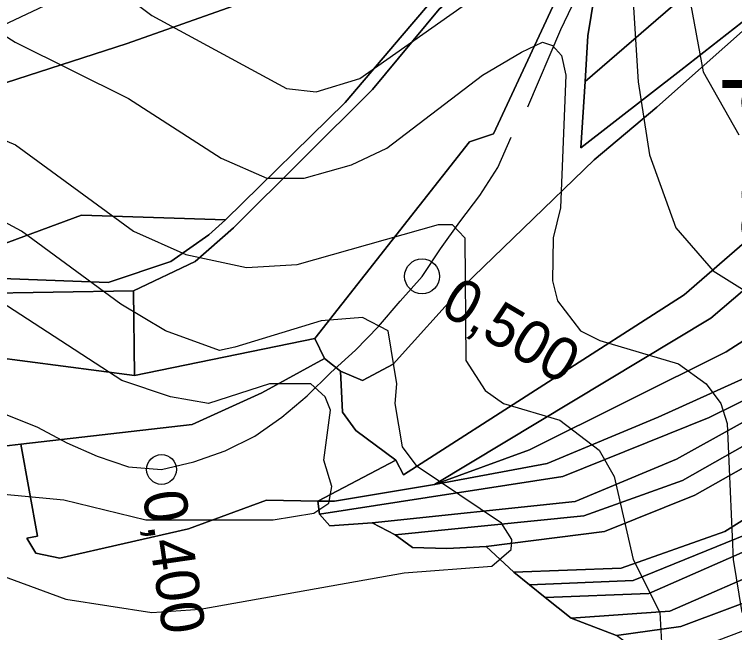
# Model space of a CAD drawing. Extents: x -510989 to -501240, y -1184665 to -1176098.
# Drawn here: x -509130.9 to -508913.6, y -1179477 to -1179290.6 of the extents above; entities that cross this region are included whole.
import ezdxf

# ---------------------------------------------------------------- set-up
doc = ezdxf.new("R2010")
doc.units = 0
for name, color, linetype in [('lesni_pozemek', 7, 'Continuous'), ('NAVRH_rozvodnice', 7, 'Continuous'), ('orna_puda', 7, 'Continuous'), ('ostatni_plocha_x_neplodna_puda', 7, 'Continuous'), ('ostatni_plocha_x_ostatni_komunikace', 7, 'Continuous'), ('STAV_systematicke_odvodneni', 7, 'Continuous'), ('STAV_vyrazne_udolnice', 7, 'Continuous'), ('trasovani_toku', 7, 'Continuous'), ('trvaly_travni_porost', 7, 'Continuous'), ('vodni_plocha_x_zamokrena_plocha', 7, 'Continuous'), ('vrstevnice_01', 7, 'Continuous'), ('vrstevnice_02', 7, 'Continuous')]:
    doc.layers.add(name, color=color, linetype=linetype)

msp = doc.modelspace()

# ---------------------------------------------------------------- linework, layer by layer
at = {"layer": 'lesni_pozemek'}
for points in [[(-508606.71, -1179124.06), (-508602.46, -1179133.28), (-508620.45, -1179146.82), (-508664.63, -1179178.45), (-508745.73, -1179236.53), (-508795.13, -1179278.48), (-508821.2, -1179300.02), (-508865.34, -1179335.02), (-508920.75, -1179382.22), (-509004.18, -1179432.41), (-509034.35, -1179437.44), (-509039.3, -1179437.44), (-509015.83, -1179425.01), (-509013.45, -1179429.49), (-508928.79, -1179375.15), (-508868.76, -1179323.15), (-508825.42, -1179288.74), (-508804.74, -1179272.32), (-508751.85, -1179228.29), (-508670.83, -1179171.13)], [(-508602.46, -1179133.28), (-508597.41, -1179144.21), (-508627.17, -1179165.02), (-508677.1, -1179199.34), (-508739.74, -1179246.04), (-508793.88, -1179292.04), (-508819.69, -1179313.98), (-508856.75, -1179347.13), (-508895.95, -1179379.44), (-508916.18, -1179392.38), (-508975.49, -1179421.94), (-509004.18, -1179432.41), (-508920.75, -1179382.22), (-508865.34, -1179335.02), (-508821.2, -1179300.02), (-508795.13, -1179278.48), (-508745.73, -1179236.53), (-508664.63, -1179178.45), (-508620.45, -1179146.82)], [(-508782.97, -1179140.01), (-508801.27, -1179151.69), (-508813.83, -1179164.87), (-508835.52, -1179196.99), (-508826.67, -1179217.53), (-508818.83, -1179228.85), (-508851, -1179251.48), (-508870.07, -1179264.89), (-508904.41, -1179287.59), (-508929.85, -1179307.42), (-508960, -1179330.91), (-508958.72, -1179310.91), (-508932.22, -1179288.07), (-508909.87, -1179281.03), (-508901.7, -1179270), (-508891.13, -1179223.99), (-508903.93, -1179198.15), (-508900.07, -1179195.8), (-508839.52, -1179165.73), (-508783.82, -1179133.81)], [(-508597.41, -1179144.21), (-508593.51, -1179152.66), (-508681.27, -1179215.37), (-508736.62, -1179256.95), (-508810.44, -1179322.38), (-508849.99, -1179360.81), (-508891.52, -1179391.72), (-508936.65, -1179412.11), (-508970.12, -1179426.03), (-509004.18, -1179432.41), (-508975.49, -1179421.94), (-508916.18, -1179392.38), (-508895.95, -1179379.44), (-508856.75, -1179347.13), (-508819.69, -1179313.98), (-508793.88, -1179292.04), (-508739.74, -1179246.04), (-508677.1, -1179199.34), (-508627.17, -1179165.02)], [(-508593.51, -1179152.66), (-508591.09, -1179157.9), (-508636.59, -1179188.7), (-508678.28, -1179219.08), (-508735.28, -1179262.56), (-508773.87, -1179296.38), (-508846.78, -1179363.36), (-508887.12, -1179395.25), (-508921.3, -1179412.21), (-508965.45, -1179429.97), (-509038.84, -1179441.31), (-509039.3, -1179437.44), (-509034.35, -1179437.44), (-509004.18, -1179432.41), (-508970.12, -1179426.03), (-508936.65, -1179412.11), (-508891.52, -1179391.72), (-508849.99, -1179360.81), (-508810.44, -1179322.38), (-508736.62, -1179256.95), (-508681.27, -1179215.37)], [(-508591.09, -1179157.9), (-508589, -1179164.01), (-508617.38, -1179182.87), (-508657.73, -1179210.41), (-508676.52, -1179223.23), (-508729.39, -1179266.54), (-508758.46, -1179289.1), (-508774.13, -1179302.13), (-508810.01, -1179338.18), (-508874.37, -1179393.27), (-508931.1, -1179424.79), (-508961.7, -1179437.48), (-509022.9, -1179443.92), (-509035.74, -1179444.84), (-509038.84, -1179441.31), (-508965.45, -1179429.97), (-508921.3, -1179412.21), (-508887.12, -1179395.25), (-508846.78, -1179363.36), (-508773.87, -1179296.38), (-508735.28, -1179262.56), (-508678.28, -1179219.08), (-508636.59, -1179188.7)], [(-508589, -1179164.01), (-508588.4, -1179169.09), (-508625.48, -1179194.26), (-508672.32, -1179226.71), (-508705.37, -1179253.14), (-508769.81, -1179304.68), (-508807.77, -1179341.74), (-508874.49, -1179400.1), (-508929.34, -1179431.21), (-508959.11, -1179441.81), (-509015.99, -1179447.57), (-509022.9, -1179443.92), (-508961.7, -1179437.48), (-508931.1, -1179424.79), (-508874.37, -1179393.27), (-508810.01, -1179338.18), (-508774.13, -1179302.13), (-508758.46, -1179289.1), (-508729.39, -1179266.54), (-508676.52, -1179223.23), (-508657.73, -1179210.41), (-508617.38, -1179182.87)], [(-508588.4, -1179169.09), (-508587.71, -1179174.96), (-508603.94, -1179186.13), (-508637.9, -1179209.19), (-508673.41, -1179233.85), (-508699.31, -1179253.96), (-508766.89, -1179308.93), (-508803.79, -1179344.12), (-508868.78, -1179403.52), (-508925.57, -1179435.6), (-508952.84, -1179446.55), (-508988.55, -1179451.08), (-509000.44, -1179451.65), (-509010.76, -1179451.37), (-509015.99, -1179447.57), (-508959.11, -1179441.81), (-508929.34, -1179431.21), (-508874.49, -1179400.1), (-508807.77, -1179341.74), (-508769.81, -1179304.68), (-508705.37, -1179253.14), (-508672.32, -1179226.71), (-508625.48, -1179194.26)], [(-508603.94, -1179186.13), (-508587.71, -1179174.96), (-508588.59, -1179186.18), (-508626.11, -1179212.1), (-508659.61, -1179236.76), (-508688.25, -1179258.6), (-508764.65, -1179319.51), (-508798.46, -1179354.18), (-508849.61, -1179401.5), (-508871.75, -1179418.41), (-508916.51, -1179446.55), (-508947.82, -1179457.65), (-508980.25, -1179458.83), (-508988.55, -1179451.08), (-508952.84, -1179446.55), (-508925.57, -1179435.6), (-508868.78, -1179403.52), (-508803.79, -1179344.12), (-508766.89, -1179308.93), (-508699.31, -1179253.96), (-508673.41, -1179233.85), (-508637.9, -1179209.19)], [(-508588.59, -1179186.18), (-508588.71, -1179193.66), (-508628.09, -1179219.81), (-508656.48, -1179239.5), (-508685.64, -1179262.11), (-508760.46, -1179322.97), (-508793.58, -1179355.94), (-508851.05, -1179409), (-508870.8, -1179423.99), (-508909.79, -1179447.4), (-508944.19, -1179461.32), (-508975.49, -1179462.64), (-508980.25, -1179458.83), (-508947.82, -1179457.65), (-508916.51, -1179446.55), (-508871.75, -1179418.41), (-508849.61, -1179401.5), (-508798.46, -1179354.18), (-508764.65, -1179319.51), (-508688.25, -1179258.6), (-508659.61, -1179236.76), (-508626.11, -1179212.1)], [(-508588.71, -1179193.66), (-508588.83, -1179200.61), (-508619.49, -1179220.52), (-508657.63, -1179249.27), (-508680.32, -1179266.36), (-508719.21, -1179297.41), (-508752.88, -1179324.28), (-508792.02, -1179362.68), (-508852.01, -1179417.08), (-508878.3, -1179434.77), (-508911.28, -1179452.86), (-508939.5, -1179465.29), (-508970.76, -1179466.44), (-508975.49, -1179462.64), (-508944.19, -1179461.32), (-508909.79, -1179447.4), (-508870.8, -1179423.99), (-508851.05, -1179409), (-508793.58, -1179355.94), (-508760.46, -1179322.97), (-508685.64, -1179262.11), (-508656.48, -1179239.5), (-508628.09, -1179219.81)], [(-508588.83, -1179200.61), (-508588.99, -1179210.23), (-508613.11, -1179226.54), (-508646.02, -1179248.81), (-508746.19, -1179326.59), (-508785.46, -1179363.77), (-508847.48, -1179420.93), (-508867.89, -1179435.75), (-508900.87, -1179456.48), (-508933.12, -1179470.58), (-508962.93, -1179472.72), (-508970.76, -1179466.44), (-508939.5, -1179465.29), (-508911.28, -1179452.86), (-508878.3, -1179434.77), (-508852.01, -1179417.08), (-508792.02, -1179362.68), (-508752.88, -1179324.28), (-508719.21, -1179297.41), (-508680.32, -1179266.36), (-508657.63, -1179249.27), (-508619.49, -1179220.52)], [(-508588.99, -1179210.23), (-508589.14, -1179219.49), (-508640.89, -1179254.11), (-508673.22, -1179276.82), (-508695.6, -1179292.56), (-508745.95, -1179333.82), (-508790.53, -1179376.59), (-508841.59, -1179423.24), (-508901.03, -1179464.49), (-508929.84, -1179475.18), (-508949.21, -1179477.96), (-508962.93, -1179472.72), (-508933.12, -1179470.58), (-508900.87, -1179456.48), (-508867.89, -1179435.75), (-508847.48, -1179420.93), (-508785.46, -1179363.77), (-508746.19, -1179326.59), (-508646.02, -1179248.81), (-508613.11, -1179226.54)], [(-508589.14, -1179219.49), (-508589.27, -1179227.34), (-508618.53, -1179246.98), (-508666.63, -1179281.56), (-508690.46, -1179299.43), (-508742.49, -1179342.95), (-508782.7, -1179379.95), (-508839.41, -1179433.04), (-508891.49, -1179469.17), (-508919.12, -1179479.61), (-508939.85, -1179484.86), (-508949.21, -1179477.96), (-508929.84, -1179475.18), (-508901.03, -1179464.49), (-508841.59, -1179423.24), (-508790.53, -1179376.59), (-508745.95, -1179333.82), (-508695.6, -1179292.56), (-508673.22, -1179276.82), (-508640.89, -1179254.11)]]:
    msp.add_lwpolyline(points, close=True, dxfattribs=at)
msp.add_lwpolyline([(-508868.76, -1179323.15), (-508928.79, -1179375.15), (-509013.45, -1179429.49), (-509015.83, -1179425.01), (-509027.91, -1179416.1), (-509031.87, -1179410.62), (-509032.48, -1179398.19), (-509025.83, -1179401.03), (-509016.58, -1179396.07), (-508995.41, -1179372.58), (-508977.42, -1179355.22), (-508955.98, -1179334.53), (-508937.07, -1179318.63), (-508909.38, -1179294.08)], dxfattribs=at)
at = {"layer": 'orna_puda'}
msp.add_lwpolyline([(-508887.74, -1179172.78), (-508963.03, -1179217.01), (-508976.41, -1179224.42), (-509025.54, -1179247.32), (-509023.73, -1179250.99), (-509015.7, -1179267.23), (-509029.73, -1179275.57), (-509096.81, -1179299.39), (-509230.1, -1179342.45)], dxfattribs=at)
at = {"layer": 'ostatni_plocha_x_neplodna_puda'}
for points in [[(-508944.97, -1179237.86), (-508944.48, -1179253.73), (-508954, -1179273.04), (-508957.84, -1179297.06), (-508958.72, -1179310.91), (-508960, -1179330.91), (-508929.85, -1179307.42), (-508904.41, -1179287.59), (-508870.07, -1179264.89), (-508851, -1179251.48), (-508849.23, -1179253.8), (-508875.96, -1179272.98), (-508909.38, -1179294.08), (-508937.07, -1179318.63), (-508955.98, -1179334.53), (-508977.42, -1179355.22), (-508995.41, -1179372.58), (-509016.58, -1179396.07), (-509025.83, -1179401.03), (-509032.48, -1179398.19), (-509037.37, -1179394.43), (-509040.27, -1179388.32), (-508993.56, -1179329.08), (-508986.39, -1179326.66)], [(-509110.64, -1179351.17), (-509067.16, -1179352.61), (-509072.25, -1179357.15), (-509083.67, -1179365.13), (-509102.55, -1179371.49), (-509137.38, -1179370.15), (-509167.51, -1179372.13)], [(-509094.91, -1179374.01), (-509094.69, -1179399.52), (-509191.61, -1179386.85), (-509194.51, -1179376.28), (-509192, -1179375.62)]]:
    msp.add_lwpolyline(points, close=True, dxfattribs=at)
at = {"layer": 'ostatni_plocha_x_ostatni_komunikace'}
msp.add_lwpolyline([(-509137.38, -1179370.15), (-509102.55, -1179371.49), (-509083.67, -1179365.13), (-509072.25, -1179357.15), (-509067.16, -1179352.61), (-509031.08, -1179317.2), (-509013.85, -1179296.97), (-509002.08, -1179283.15), (-508989.24, -1179271.89), (-508978.81, -1179257.56), (-508978.56, -1179251.27), (-508972.56, -1179241.6), (-508938.85, -1179219.35), (-508939.6, -1179224.99), (-508967.66, -1179254.61), (-508979.52, -1179264.32), (-508988.46, -1179276.81), (-509002.76, -1179289.1), (-509022.84, -1179313.28), (-509064.81, -1179355.04), (-509076.39, -1179365.13), (-509094.91, -1179374.01), (-509192, -1179375.62)], dxfattribs=at)
at = {"layer": 'STAV_systematicke_odvodneni'}
msp.add_line((-509228.03, -1179338.07), (-509023.75, -1179241.74), dxfattribs=at)
at = {"layer": 'STAV_vyrazne_udolnice'}
msp.add_lwpolyline([(-508976.03, -1179318.51), (-508965.98, -1179295.21), (-508953.52, -1179269.1), (-508937.85, -1179250.22), (-508920.97, -1179229.73), (-508906.1, -1179208.44)], dxfattribs=at)
at = {"layer": 'trasovani_toku'}
for p, q in [((-508985.04, -1179336.82), (-508980.98, -1179327.68)), ((-508990.49, -1179345.2), (-508985.04, -1179336.82)), ((-508996.51, -1179353.19), (-508990.49, -1179345.2)), ((-509002.37, -1179361.29), (-508996.51, -1179353.19)), ((-509007.9, -1179369.62), (-509002.37, -1179361.29)), ((-509014.48, -1179377.15), (-509007.9, -1179369.62)), ((-509021, -1179384.73), (-509014.48, -1179377.15)), ((-509027.98, -1179391.89), (-509021, -1179384.73)), ((-509035.4, -1179398.6), (-509027.98, -1179391.89)), ((-509042.52, -1179405.62), (-509035.4, -1179398.6)), ((-509050.19, -1179412.04), (-509042.52, -1179405.62)), ((-509133.15, -1179411.34), (-509123.9, -1179415.13)), ((-509058.33, -1179417.84), (-509050.19, -1179412.04)), ((-509123.9, -1179415.13), (-509115.05, -1179419.8)), ((-509067.3, -1179422.27), (-509058.33, -1179417.84)), ((-509115.05, -1179419.8), (-509105.91, -1179423.85)), ((-509076.74, -1179425.55), (-509067.3, -1179422.27)), ((-509105.91, -1179423.85), (-509096.45, -1179427.08)), ((-509086.48, -1179427.84), (-509076.74, -1179425.55)), ((-509096.45, -1179427.08), (-509086.48, -1179427.84))]:
    msp.add_line(p, q, dxfattribs=at)
for centre, radius in [((-509007.9, -1179369.62), 5.25), ((-509086.48, -1179427.84), 4.5)]:
    msp.add_circle(centre, radius, dxfattribs=at)
at = {"layer": 'trvaly_travni_porost'}
for points in [[(-508938.85, -1179219.35), (-508903.93, -1179198.15), (-508891.13, -1179223.99), (-508901.7, -1179270), (-508909.87, -1179281.03), (-508932.22, -1179288.07), (-508958.72, -1179310.91), (-508957.84, -1179297.06), (-508954, -1179273.04), (-508944.48, -1179253.73), (-508944.97, -1179237.86), (-508939.6, -1179224.99)], [(-508939.6, -1179224.99), (-508944.97, -1179237.86), (-508986.39, -1179326.66), (-508993.56, -1179329.08), (-509040.27, -1179388.32), (-509094.69, -1179399.52), (-509094.91, -1179374.01), (-509076.39, -1179365.13), (-509064.81, -1179355.04), (-509022.84, -1179313.28), (-509002.76, -1179289.1), (-508988.46, -1179276.81), (-508979.52, -1179264.32), (-508967.66, -1179254.61)], [(-508978.56, -1179251.27), (-508978.81, -1179257.56), (-508989.24, -1179271.89), (-509002.08, -1179283.15), (-509013.85, -1179296.97), (-509031.08, -1179317.2), (-509067.16, -1179352.61), (-509110.64, -1179351.17), (-509167.51, -1179372.13), (-509195.12, -1179373.77), (-509206.62, -1179374.96), (-509242.33, -1179383.33), (-509269.44, -1179393.92), (-509284.22, -1179362), (-509230.1, -1179342.45), (-509096.81, -1179299.39), (-509029.73, -1179275.57), (-509015.7, -1179267.23), (-508972.56, -1179241.6)]]:
    msp.add_lwpolyline(points, close=True, dxfattribs=at)
msp.add_lwpolyline([(-509207.65, -1179429.48), (-509128.96, -1179420.22), (-509123.91, -1179447.96), (-509127.12, -1179448.54), (-509124.38, -1179453.12), (-509117.16, -1179454.58), (-509078.31, -1179445.75), (-509054.83, -1179437.12), (-509039.3, -1179437.44), (-509038.84, -1179441.31), (-509035.74, -1179444.84), (-509022.9, -1179443.92), (-509015.99, -1179447.57), (-509010.76, -1179451.37), (-509000.44, -1179451.65), (-508988.55, -1179451.08), (-508980.25, -1179458.83), (-508975.49, -1179462.64), (-508970.76, -1179466.44), (-508962.93, -1179472.72), (-508949.21, -1179477.96)], dxfattribs=at)
at = {"layer": 'vodni_plocha_x_zamokrena_plocha'}
for points in [[(-509194.51, -1179376.28), (-509191.61, -1179386.85), (-509094.69, -1179399.52), (-509040.27, -1179388.32), (-509037.37, -1179394.43), (-509056.26, -1179404.79), (-509077.25, -1179414.3), (-509128.96, -1179420.22), (-509207.65, -1179429.48), (-509209.73, -1179422.33), (-509221.07, -1179383.22)], [(-509032.48, -1179398.19), (-509031.87, -1179410.62), (-509027.91, -1179416.1), (-509015.83, -1179425.01), (-509039.3, -1179437.44), (-509054.83, -1179437.12), (-509078.31, -1179445.75), (-509117.16, -1179454.58), (-509124.38, -1179453.12), (-509127.12, -1179448.54), (-509123.91, -1179447.96), (-509128.96, -1179420.22), (-509077.25, -1179414.3), (-509056.26, -1179404.79), (-509037.37, -1179394.43)]]:
    msp.add_lwpolyline(points, close=True, dxfattribs=at)
at = {"layer": 'vrstevnice_01'}
for points in [[(-509060.31, -1179009), (-509071.5, -1179024), (-509079.59, -1179045), (-509086.59, -1179089), (-509093.69, -1179117), (-509110.31, -1179158), (-509122.31, -1179180), (-509129.81, -1179192), (-509157.19, -1179220), (-509167.09, -1179232), (-509170.91, -1179239), (-509172.81, -1179256), (-509171.31, -1179262), (-509166.91, -1179271), (-509161.81, -1179277), (-509150.91, -1179286), (-509130.69, -1179299), (-509096.5, -1179316), (-509068.5, -1179334), (-509054.69, -1179340), (-509043.5, -1179340), (-509029.19, -1179336), (-509018.5, -1179331)], [(-508927.31, -1179285), (-508923.09, -1179308)], [(-509018.5, -1179331), (-508989.69, -1179309), (-508977.91, -1179302), (-508971.59, -1179299), (-508968.59, -1179300), (-508965.81, -1179303), (-508964.5, -1179309), (-508966.09, -1179349), (-508968.31, -1179358), (-508968.59, -1179371), (-508967, -1179377), (-508960.09, -1179386), (-508954.31, -1179389), (-508930.5, -1179396), (-508922.19, -1179402), (-508917.81, -1179408), (-508915.81, -1179414), (-508914, -1179455), (-508911.41, -1179471)], [(-508923.09, -1179308), (-508912.31, -1179327)], [(-509013.31, -1179459), (-508986.81, -1179457), (-508981, -1179452), (-508980.81, -1179449), (-508983.91, -1179444), (-509009.41, -1179427), (-509013.81, -1179421), (-509016, -1179408), (-509015.5, -1179402), (-509018.09, -1179386), (-509025.91, -1179382), (-509038.31, -1179383), (-509064.41, -1179391), (-509069, -1179392), (-509085.31, -1179386), (-509098.81, -1179378), (-509128.69, -1179356), (-509151.09, -1179344)], [(-509206.31, -1179490), (-509190.69, -1179466), (-509187.69, -1179463), (-509172.91, -1179459), (-509156.09, -1179458), (-509139.81, -1179458), (-509115.41, -1179467), (-509089.41, -1179471), (-509074.81, -1179470), (-509013.31, -1179459)]]:
    msp.add_lwpolyline(points, dxfattribs=at)
at = {"layer": 'vrstevnice_02'}
for points in [[(-509109.31, -1179276), (-509089.41, -1179291), (-509048.81, -1179313), (-509039.81, -1179314), (-509026.69, -1179310), (-508971.31, -1179271)], [(-508945, -1179274), (-508942.69, -1179311), (-508939.31, -1179333), (-508931.31, -1179355), (-508920.09, -1179368), (-508908.81, -1179375)], [(-509154.19, -1179320), (-509130.59, -1179330), (-509094.91, -1179356), (-509079.19, -1179363), (-509060.81, -1179367), (-509045.59, -1179366), (-509002.91, -1179354), (-508998.81, -1179354), (-508995, -1179358), (-508994.69, -1179395), (-508988.81, -1179404), (-508983.31, -1179408), (-508966.31, -1179413), (-508954.5, -1179422), (-508949.91, -1179430), (-508944.19, -1179455), (-508936.19, -1179471), (-508935.69, -1179480)], [(-509158.59, -1179433), (-509116, -1179437), (-509091.19, -1179443), (-509052.81, -1179443), (-509040.5, -1179441), (-509036, -1179438), (-509035.09, -1179433), (-509037.5, -1179425), (-509035.5, -1179410), (-509037.09, -1179406), (-509041.41, -1179402), (-509053.91, -1179402), (-509072.31, -1179408), (-509083.81, -1179406), (-509098.5, -1179401), (-509149.41, -1179368)]]:
    msp.add_lwpolyline(points, dxfattribs=at)

# ---------------------------------------------------------------- texts
at = {"layer": 'NAVRH_rozvodnice'}
msp.add_text('přítok "K"', height=20, rotation=270, dxfattribs=at).set_placement((-508911.3, -1179308.66))
at = {"layer": 'trasovani_toku'}
for s, rotation, p in [('0,500', 329.5637, (-509003.04, -1179380.38)), ('0,400', 278.2725, (-509092.22, -1179435.06))]:
    msp.add_text(s, height=13, rotation=rotation, dxfattribs=at).set_placement(p)

doc.saveas('drawing.dxf')
